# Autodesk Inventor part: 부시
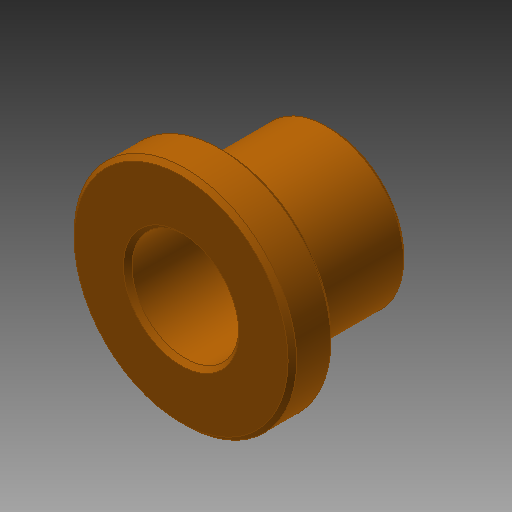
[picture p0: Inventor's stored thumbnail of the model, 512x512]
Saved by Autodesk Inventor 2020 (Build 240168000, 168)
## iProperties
Created: 2015-10
Part Number: 부시
Document SubType Name: Modeling
Designer: mdu
Density: 7.86 g/cm^3
Material: 황동, 연질
Mass: 246.97 g
Surface Area: 129.264 cm^2
Volume: 31.4212 cm^3
Appearance: 주황색
Author: mdu
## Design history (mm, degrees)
sketch "스케치1"
  geometry: C1 r 31 at (0, 0) reference; C2 r 25 at (0, 0) reference; C3 r 30 at (0, 0) reference; C4 r 26 at (0, 0); C5 r 18 at (0, 0); 1 further point
  constraints: 2 centre point, 2 coincident
  dimensions: "d20" = 5 radial gap between concentric circles of C1 C4; "d21" = 8 radial gap between concentric circles of C5 C4
  node "참조1"
  node "참조2"
  node "참조4"
extrude "돌출1" new body sketch "스케치1" distance "d0" = 10; taper "d1" = 0 deg
extrude "돌출2" join sketch "스케치1" distance "d2" = 35; taper "d3" = 0 deg
sketch "스케치4"
  geometry: C1 r 12.5 at (0, 0); 1 further point
  constraints: 1 centre point, 1 coincident
  dimensions: "d24" = 25 diameter of C1
extrude "돌출5" cut sketch "스케치4" extent not by distance; stored distance "d25" = 10; taper "d26" = 0 deg
chamfer "모따기1" distance "d6" = 1; stored, may be unused: second distance "d7" = 2, angle "d8" = 45 deg
node "솔리드1"
